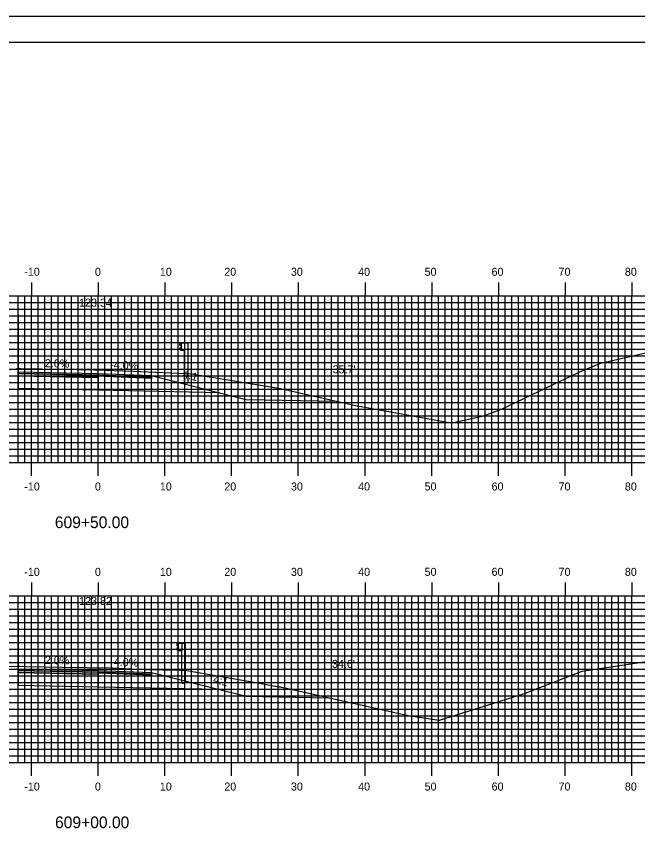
# Model space of a CAD drawing. Extents: x 842962 to 843305, y 363538 to 363758.
# Drawn here: x 843115.7 to 843208.7, y 363633.7 to 363757.6 of the extents above; entities that cross this region are included whole.
import ezdxf

# ---------------------------------------------------------------- set-up
doc = ezdxf.new("R2010")
doc.units = 0
for name, color, linetype in [('ANNOTATION', 7, 'Continuous'), ('BORDER', 7, 'Continuous'), ('D_Roadway_Centerline_Text', 7, 'Continuous'), ('D_Roadway_Edge_Shoulder', 7, 'Continuous'), ('D_Roadway_Edge_TW', 7, 'Continuous'), ('D_Roadway_FinishedGrade', 7, 'Continuous'), ('D_Roadway_Pavement', 7, 'Continuous'), ('D_Roadway_SubGrade', 7, 'Continuous'), ('D_Text_Standard', 7, 'Continuous'), ('H_V ANNOTATION', 7, 'Continuous'), ('M_Guardrail', 7, 'Continuous'), ('M_Roadway_Centerline', 7, 'Continuous'), ('MAJOR', 7, 'Continuous'), ('MINOR', 7, 'Continuous'), ('PLOT BOUNDARY', 7, 'Continuous'), ('S_Roadway_Centerline', 7, 'Continuous')]:
    doc.layers.add(name, color=color, linetype=linetype)

msp = doc.modelspace()

# ---------------------------------------------------------------- linework, layer by layer
at = {"layer": 'BORDER'}
msp.add_lwpolyline([(842978.31, 363543.72), (843298.31, 363543.72), (843298.31, 363753.72), (842978.31, 363753.72)], close=True, dxfattribs=at)
at = {"layer": 'D_Roadway_Edge_Shoulder'}
for p, q in [((843115.91, 363704.05), (843115.91, 363704.3)), ((843115.91, 363659.53), (843115.91, 363659.78))]:
    msp.add_line(p, q, dxfattribs=at)
for points in [[(843127.91, 363704.06), (843135.91, 363703.74), (843135.91, 363703.49), (843127.91, 363703.81)], [(843127.91, 363659.54), (843135.91, 363659.22), (843135.91, 363658.97), (843127.91, 363659.29)]]:
    msp.add_lwpolyline(points, close=True, dxfattribs=at)
at = {"layer": 'D_Roadway_Edge_TW'}
for points in [[(843115.91, 363704.3), (843127.91, 363704.06), (843127.91, 363703.81), (843115.91, 363704.05)], [(843115.91, 363659.78), (843127.91, 363659.54), (843127.91, 363659.29), (843115.91, 363659.53)]]:
    msp.add_lwpolyline(points, close=True, dxfattribs=at)
at = {"layer": 'D_Roadway_FinishedGrade'}
for points in [[(843146.09, 363701.19), (843150.08, 363700.19), (843163.64, 363699.92)], [(843146.09, 363656.68), (843150.08, 363655.68), (843162.48, 363655.43)]]:
    msp.add_lwpolyline(points, dxfattribs=at)
at = {"layer": 'D_Roadway_Pavement'}
for p, q in [((843115.91, 363703.71), (843115.91, 363704.05)), ((843115.91, 363659.2), (843115.91, 363659.53))]:
    msp.add_line(p, q, dxfattribs=at)
for points in [[(843115.91, 363704.05), (843127.91, 363703.81), (843127.91, 363703.47), (843115.91, 363703.71)], [(843127.91, 363703.81), (843135.91, 363703.49), (843135.91, 363703.32), (843127.91, 363703.64)], [(843115.91, 363659.53), (843127.91, 363659.29), (843127.91, 363658.96), (843115.91, 363659.2)], [(843127.91, 363659.29), (843135.91, 363658.97), (843135.91, 363658.8), (843127.91, 363659.12)]]:
    msp.add_lwpolyline(points, close=True, dxfattribs=at)
for points in [[(843127.91, 363703.81), (843127.91, 363703.47)], [(843127.91, 363703.81), (843127.91, 363703.47)], [(843127.91, 363659.29), (843127.91, 363658.96)], [(843127.91, 363659.29), (843127.91, 363658.96)]]:
    msp.add_lwpolyline(points, dxfattribs=at)
at = {"layer": 'D_Roadway_SubGrade'}
for p, q in [((843115.91, 363712.89), (843115.91, 363701.8)), ((843115.91, 363701.8), (843115.91, 363703.71)), ((843115.91, 363668.38), (843115.91, 363657.28)), ((843115.91, 363657.28), (843115.91, 363659.2))]:
    msp.add_line(p, q, dxfattribs=at)
for points in [[(843115.91, 363703.71), (843127.91, 363703.47), (843127.91, 363701.56), (843115.91, 363701.8)], [(843127.91, 363703.47), (843127.91, 363703.81), (843135.91, 363703.49), (843135.91, 363703.74), (843146.09, 363701.19), (843127.91, 363701.56)], [(843115.91, 363659.2), (843127.91, 363658.96), (843127.91, 363657.04), (843115.91, 363657.28)], [(843127.91, 363658.96), (843127.91, 363659.29), (843135.91, 363658.97), (843135.91, 363659.22), (843146.09, 363656.68), (843127.91, 363657.04)]]:
    msp.add_lwpolyline(points, close=True, dxfattribs=at)
at = {"layer": 'M_Guardrail'}
for p, q in [((843140.28, 363708.57), (843140.13, 363708.47)), ((843140.13, 363708.32), (843140.33, 363708.19)), ((843140.33, 363707.97), (843140.13, 363707.83)), ((843140.38, 363708.59), (843140.29, 363708.57)), ((843140.36, 363708.12), (843140.36, 363708.03)), ((843140.38, 363708.66), (843140.87, 363708.66)), ((843140.38, 363707.49), (843140.38, 363708.66)), ((843140.87, 363708.66), (843141.36, 363708.66)), ((843140.87, 363708.66), (843140.87, 363707.49)), ((843141.36, 363708.66), (843141.36, 363702.66)), ((843140.13, 363707.69), (843140.28, 363707.59)), ((843140.29, 363707.58), (843140.38, 363707.57)), ((843140.87, 363707.49), (843140.38, 363707.49)), ((843140.87, 363702.66), (843140.87, 363707.49)), ((843140.87, 363702.66), (843141.36, 363702.66)), ((843139.86, 363663.55), (843139.72, 363663.45)), ((843139.96, 363663.57), (843139.88, 363663.56)), ((843139.96, 363663.64), (843140.45, 363663.64)), ((843139.96, 363662.48), (843139.96, 363663.64)), ((843140.45, 363663.64), (843140.94, 363663.64)), ((843140.45, 363663.64), (843140.45, 363662.48)), ((843140.94, 363663.64), (843140.94, 363657.64)), ((843139.72, 363663.31), (843139.91, 363663.17)), ((843139.91, 363662.95), (843139.72, 363662.82)), ((843139.72, 363662.67), (843139.86, 363662.57)), ((843139.88, 363662.57), (843139.96, 363662.55)), ((843139.95, 363663.11), (843139.95, 363663.02)), ((843140.45, 363662.48), (843139.96, 363662.48)), ((843140.45, 363657.64), (843140.45, 363662.48)), ((843140.45, 363657.64), (843140.94, 363657.64))]:
    msp.add_line(p, q, dxfattribs=at)
for centre, major_axis, start_param, end_param in [((843140.18, 363708.39), (-0.0877, 0), 5.323254, 7.243116), ((843140.3, 363708.53), (-0.0417, 0), 4.886922, 5.323254), ((843140.28, 363708.12), (0.0789, 0), 0, 0.959931), ((843140.28, 363708.03), (0.0789, 0), 5.323254, 6.283185), ((843140.18, 363707.76), (-0.0877, 0), 5.323254, 7.243116), ((843140.3, 363707.62), (-0.0417, 0), 0.959931, 1.396263), ((843139.77, 363663.38), (-0.0877, 0), 5.323254, 7.243116), ((843139.89, 363663.52), (-0.0417, 0), 4.886922, 5.323254), ((843139.77, 363662.74), (-0.0877, 0), 5.323254, 7.243116), ((843139.89, 363662.61), (-0.0417, 0), 0.959931, 1.396263), ((843139.87, 363663.11), (0.0789, 0), 0, 0.959931), ((843139.87, 363663.02), (0.0789, 0), 5.323254, 6.283185)]:
    msp.add_ellipse(centre, major_axis=major_axis, ratio=0.995501, start_param=start_param, end_param=end_param, dxfattribs=at)
at = {"layer": 'MAJOR'}
for p, q in [((843117.91, 363717.73), (843117.91, 363715.72)), ((843127.91, 363717.73), (843127.91, 363715.72)), ((843137.91, 363717.73), (843137.91, 363715.72)), ((843147.91, 363717.73), (843147.91, 363715.72)), ((843157.91, 363717.73), (843157.91, 363715.72)), ((843167.91, 363717.73), (843167.91, 363715.72)), ((843177.91, 363717.73), (843177.91, 363715.72)), ((843187.91, 363717.73), (843187.91, 363715.72)), ((843197.91, 363717.73), (843197.91, 363715.72)), ((843207.91, 363717.73), (843207.91, 363715.72)), ((842987.91, 363715.72), (843267.91, 363715.72)), ((842987.91, 363715.72), (843267.91, 363715.72)), ((843117.91, 363690.72), (843117.91, 363715.72)), ((843127.91, 363690.72), (843127.91, 363715.72)), ((843137.91, 363690.72), (843137.91, 363715.72)), ((843147.91, 363690.72), (843147.91, 363715.72)), ((843157.91, 363690.72), (843157.91, 363715.72)), ((843167.91, 363690.72), (843167.91, 363715.72)), ((843177.91, 363690.72), (843177.91, 363715.72)), ((843187.91, 363690.72), (843187.91, 363715.72)), ((843197.91, 363690.72), (843197.91, 363715.72)), ((843207.91, 363690.72), (843207.91, 363715.72)), ((842987.91, 363710.72), (843267.91, 363710.72)), ((842987.91, 363705.72), (843267.91, 363705.72)), ((842987.91, 363700.72), (843267.91, 363700.72)), ((842987.91, 363695.72), (843267.91, 363695.72)), ((842987.91, 363690.72), (843267.91, 363690.72)), ((842987.91, 363690.72), (843267.91, 363690.72)), ((843117.91, 363688.72), (843117.91, 363690.72)), ((843127.91, 363688.72), (843127.91, 363690.72)), ((843137.91, 363688.72), (843137.91, 363690.72)), ((843147.91, 363688.72), (843147.91, 363690.72)), ((843157.91, 363688.72), (843157.91, 363690.72)), ((843167.91, 363688.72), (843167.91, 363690.72)), ((843177.91, 363688.72), (843177.91, 363690.72)), ((843187.91, 363688.72), (843187.91, 363690.72)), ((843197.91, 363688.72), (843197.91, 363690.72)), ((843207.91, 363688.72), (843207.91, 363690.72)), ((843117.91, 363672.73), (843117.91, 363670.72)), ((843127.91, 363672.73), (843127.91, 363670.72)), ((843137.91, 363672.73), (843137.91, 363670.72)), ((843147.91, 363672.73), (843147.91, 363670.72)), ((843157.91, 363672.73), (843157.91, 363670.72)), ((843167.91, 363672.73), (843167.91, 363670.72)), ((843177.91, 363672.73), (843177.91, 363670.72)), ((843187.91, 363672.73), (843187.91, 363670.72)), ((843197.91, 363672.73), (843197.91, 363670.72)), ((843207.91, 363672.73), (843207.91, 363670.72)), ((842987.91, 363670.72), (843267.91, 363670.72)), ((842987.91, 363670.72), (843267.91, 363670.72)), ((843117.91, 363645.72), (843117.91, 363670.72)), ((843127.91, 363645.72), (843127.91, 363670.72)), ((843137.91, 363645.72), (843137.91, 363670.72)), ((843147.91, 363645.72), (843147.91, 363670.72)), ((843157.91, 363645.72), (843157.91, 363670.72)), ((843167.91, 363645.72), (843167.91, 363670.72)), ((843177.91, 363645.72), (843177.91, 363670.72)), ((843187.91, 363645.72), (843187.91, 363670.72)), ((843197.91, 363645.72), (843197.91, 363670.72)), ((843207.91, 363645.72), (843207.91, 363670.72)), ((842987.91, 363665.72), (843267.91, 363665.72)), ((842987.91, 363660.72), (843267.91, 363660.72)), ((842987.91, 363655.72), (843267.91, 363655.72)), ((842987.91, 363650.72), (843267.91, 363650.72)), ((842987.91, 363645.72), (843267.91, 363645.72)), ((842987.91, 363645.72), (843267.91, 363645.72)), ((843117.91, 363643.72), (843117.91, 363645.72)), ((843127.91, 363643.72), (843127.91, 363645.72)), ((843137.91, 363643.72), (843137.91, 363645.72)), ((843147.91, 363643.72), (843147.91, 363645.72)), ((843157.91, 363643.72), (843157.91, 363645.72)), ((843167.91, 363643.72), (843167.91, 363645.72)), ((843177.91, 363643.72), (843177.91, 363645.72)), ((843187.91, 363643.72), (843187.91, 363645.72)), ((843197.91, 363643.72), (843197.91, 363645.72)), ((843207.91, 363643.72), (843207.91, 363645.72))]:
    msp.add_line(p, q, dxfattribs=at)
at = {"layer": 'MINOR'}
for p, q in [((843115.91, 363690.72), (843115.91, 363715.72)), ((843116.91, 363690.72), (843116.91, 363715.72)), ((843118.91, 363690.72), (843118.91, 363715.72)), ((843119.91, 363690.72), (843119.91, 363715.72)), ((843120.91, 363690.72), (843120.91, 363715.72)), ((843121.91, 363690.72), (843121.91, 363715.72)), ((843122.91, 363690.72), (843122.91, 363715.72)), ((843123.91, 363690.72), (843123.91, 363715.72)), ((843124.91, 363690.72), (843124.91, 363715.72)), ((843125.91, 363690.72), (843125.91, 363715.72)), ((843126.91, 363690.72), (843126.91, 363715.72)), ((843128.91, 363690.72), (843128.91, 363715.72)), ((843129.91, 363690.72), (843129.91, 363715.72)), ((843130.91, 363690.72), (843130.91, 363715.72)), ((843131.91, 363690.72), (843131.91, 363715.72)), ((843132.91, 363690.72), (843132.91, 363715.72)), ((843133.91, 363690.72), (843133.91, 363715.72)), ((843134.91, 363690.72), (843134.91, 363715.72)), ((843135.91, 363690.72), (843135.91, 363715.72)), ((843136.91, 363690.72), (843136.91, 363715.72)), ((843138.91, 363690.72), (843138.91, 363715.72)), ((843139.91, 363690.72), (843139.91, 363715.72)), ((843140.91, 363690.72), (843140.91, 363715.72)), ((843141.91, 363690.72), (843141.91, 363715.72)), ((843142.91, 363690.72), (843142.91, 363715.72)), ((843143.91, 363690.72), (843143.91, 363715.72)), ((843144.91, 363690.72), (843144.91, 363715.72)), ((843145.91, 363690.72), (843145.91, 363715.72)), ((843146.91, 363690.72), (843146.91, 363715.72)), ((843148.91, 363690.72), (843148.91, 363715.72)), ((843149.91, 363690.72), (843149.91, 363715.72)), ((843150.91, 363690.72), (843150.91, 363715.72)), ((843151.91, 363690.72), (843151.91, 363715.72)), ((843152.91, 363690.72), (843152.91, 363715.72)), ((843153.91, 363690.72), (843153.91, 363715.72)), ((843154.91, 363690.72), (843154.91, 363715.72)), ((843155.91, 363690.72), (843155.91, 363715.72)), ((843156.91, 363690.72), (843156.91, 363715.72)), ((843158.91, 363690.72), (843158.91, 363715.72)), ((843159.91, 363690.72), (843159.91, 363715.72)), ((843160.91, 363690.72), (843160.91, 363715.72)), ((843161.91, 363690.72), (843161.91, 363715.72)), ((843162.91, 363690.72), (843162.91, 363715.72)), ((843163.91, 363690.72), (843163.91, 363715.72)), ((843164.91, 363690.72), (843164.91, 363715.72)), ((843165.91, 363690.72), (843165.91, 363715.72)), ((843166.91, 363690.72), (843166.91, 363715.72)), ((843168.91, 363690.72), (843168.91, 363715.72)), ((843169.91, 363690.72), (843169.91, 363715.72)), ((843170.91, 363690.72), (843170.91, 363715.72)), ((843171.91, 363690.72), (843171.91, 363715.72)), ((843172.91, 363690.72), (843172.91, 363715.72)), ((843173.91, 363690.72), (843173.91, 363715.72)), ((843174.91, 363690.72), (843174.91, 363715.72)), ((843175.91, 363690.72), (843175.91, 363715.72)), ((843176.91, 363690.72), (843176.91, 363715.72)), ((843178.91, 363690.72), (843178.91, 363715.72)), ((843179.91, 363690.72), (843179.91, 363715.72)), ((843180.91, 363690.72), (843180.91, 363715.72)), ((843181.91, 363690.72), (843181.91, 363715.72)), ((843182.91, 363690.72), (843182.91, 363715.72)), ((843183.91, 363690.72), (843183.91, 363715.72)), ((843184.91, 363690.72), (843184.91, 363715.72)), ((843185.91, 363690.72), (843185.91, 363715.72)), ((843186.91, 363690.72), (843186.91, 363715.72)), ((843188.91, 363690.72), (843188.91, 363715.72)), ((843189.91, 363690.72), (843189.91, 363715.72)), ((843190.91, 363690.72), (843190.91, 363715.72)), ((843191.91, 363690.72), (843191.91, 363715.72)), ((843192.91, 363690.72), (843192.91, 363715.72)), ((843193.91, 363690.72), (843193.91, 363715.72)), ((843194.91, 363690.72), (843194.91, 363715.72)), ((843195.91, 363690.72), (843195.91, 363715.72)), ((843196.91, 363690.72), (843196.91, 363715.72)), ((843198.91, 363690.72), (843198.91, 363715.72)), ((843199.91, 363690.72), (843199.91, 363715.72)), ((843200.91, 363690.72), (843200.91, 363715.72)), ((843201.91, 363690.72), (843201.91, 363715.72)), ((843202.91, 363690.72), (843202.91, 363715.72)), ((843203.91, 363690.72), (843203.91, 363715.72)), ((843204.91, 363690.72), (843204.91, 363715.72)), ((843205.91, 363690.72), (843205.91, 363715.72)), ((843206.91, 363690.72), (843206.91, 363715.72)), ((842987.91, 363714.72), (843267.91, 363714.72)), ((842987.91, 363713.72), (843267.91, 363713.72)), ((842987.91, 363712.72), (843267.91, 363712.72)), ((842987.91, 363711.72), (843267.91, 363711.72)), ((842987.91, 363709.72), (843267.91, 363709.72)), ((842987.91, 363708.72), (843267.91, 363708.72)), ((842987.91, 363707.72), (843267.91, 363707.72)), ((842987.91, 363706.72), (843267.91, 363706.72)), ((842987.91, 363704.72), (843267.91, 363704.72)), ((842987.91, 363703.72), (843267.91, 363703.72)), ((842987.91, 363702.72), (843267.91, 363702.72)), ((842987.91, 363701.72), (843267.91, 363701.72)), ((842987.91, 363699.72), (843267.91, 363699.72)), ((842987.91, 363698.72), (843267.91, 363698.72)), ((842987.91, 363697.72), (843267.91, 363697.72)), ((842987.91, 363696.72), (843267.91, 363696.72)), ((842987.91, 363694.72), (843267.91, 363694.72)), ((842987.91, 363693.72), (843267.91, 363693.72)), ((842987.91, 363692.72), (843267.91, 363692.72)), ((842987.91, 363691.72), (843267.91, 363691.72)), ((842987.91, 363669.72), (843267.91, 363669.72)), ((843115.91, 363645.72), (843115.91, 363670.72)), ((843116.91, 363645.72), (843116.91, 363670.72)), ((843118.91, 363645.72), (843118.91, 363670.72)), ((843119.91, 363645.72), (843119.91, 363670.72)), ((843120.91, 363645.72), (843120.91, 363670.72)), ((843121.91, 363645.72), (843121.91, 363670.72)), ((843122.91, 363645.72), (843122.91, 363670.72)), ((843123.91, 363645.72), (843123.91, 363670.72)), ((843124.91, 363645.72), (843124.91, 363670.72)), ((843125.91, 363645.72), (843125.91, 363670.72)), ((843126.91, 363645.72), (843126.91, 363670.72)), ((843128.91, 363645.72), (843128.91, 363670.72)), ((843129.91, 363645.72), (843129.91, 363670.72)), ((843130.91, 363645.72), (843130.91, 363670.72)), ((843131.91, 363645.72), (843131.91, 363670.72)), ((843132.91, 363645.72), (843132.91, 363670.72)), ((843133.91, 363645.72), (843133.91, 363670.72)), ((843134.91, 363645.72), (843134.91, 363670.72)), ((843135.91, 363645.72), (843135.91, 363670.72)), ((843136.91, 363645.72), (843136.91, 363670.72)), ((843138.91, 363645.72), (843138.91, 363670.72)), ((843139.91, 363645.72), (843139.91, 363670.72)), ((843140.91, 363645.72), (843140.91, 363670.72)), ((843141.91, 363645.72), (843141.91, 363670.72)), ((843142.91, 363645.72), (843142.91, 363670.72)), ((843143.91, 363645.72), (843143.91, 363670.72)), ((843144.91, 363645.72), (843144.91, 363670.72)), ((843145.91, 363645.72), (843145.91, 363670.72)), ((843146.91, 363645.72), (843146.91, 363670.72)), ((843148.91, 363645.72), (843148.91, 363670.72)), ((843149.91, 363645.72), (843149.91, 363670.72)), ((843150.91, 363645.72), (843150.91, 363670.72)), ((843151.91, 363645.72), (843151.91, 363670.72)), ((843152.91, 363645.72), (843152.91, 363670.72)), ((843153.91, 363645.72), (843153.91, 363670.72)), ((843154.91, 363645.72), (843154.91, 363670.72)), ((843155.91, 363645.72), (843155.91, 363670.72)), ((843156.91, 363645.72), (843156.91, 363670.72)), ((843158.91, 363645.72), (843158.91, 363670.72)), ((843159.91, 363645.72), (843159.91, 363670.72)), ((843160.91, 363645.72), (843160.91, 363670.72)), ((843161.91, 363645.72), (843161.91, 363670.72)), ((843162.91, 363645.72), (843162.91, 363670.72)), ((843163.91, 363645.72), (843163.91, 363670.72)), ((843164.91, 363645.72), (843164.91, 363670.72)), ((843165.91, 363645.72), (843165.91, 363670.72)), ((843166.91, 363645.72), (843166.91, 363670.72)), ((843168.91, 363645.72), (843168.91, 363670.72)), ((843169.91, 363645.72), (843169.91, 363670.72)), ((843170.91, 363645.72), (843170.91, 363670.72)), ((843171.91, 363645.72), (843171.91, 363670.72)), ((843172.91, 363645.72), (843172.91, 363670.72)), ((843173.91, 363645.72), (843173.91, 363670.72)), ((843174.91, 363645.72), (843174.91, 363670.72)), ((843175.91, 363645.72), (843175.91, 363670.72)), ((843176.91, 363645.72), (843176.91, 363670.72)), ((843178.91, 363645.72), (843178.91, 363670.72)), ((843179.91, 363645.72), (843179.91, 363670.72)), ((843180.91, 363645.72), (843180.91, 363670.72)), ((843181.91, 363645.72), (843181.91, 363670.72)), ((843182.91, 363645.72), (843182.91, 363670.72)), ((843183.91, 363645.72), (843183.91, 363670.72)), ((843184.91, 363645.72), (843184.91, 363670.72)), ((843185.91, 363645.72), (843185.91, 363670.72)), ((843186.91, 363645.72), (843186.91, 363670.72)), ((843188.91, 363645.72), (843188.91, 363670.72)), ((843189.91, 363645.72), (843189.91, 363670.72)), ((843190.91, 363645.72), (843190.91, 363670.72)), ((843191.91, 363645.72), (843191.91, 363670.72)), ((843192.91, 363645.72), (843192.91, 363670.72)), ((843193.91, 363645.72), (843193.91, 363670.72)), ((843194.91, 363645.72), (843194.91, 363670.72)), ((843195.91, 363645.72), (843195.91, 363670.72)), ((843196.91, 363645.72), (843196.91, 363670.72)), ((843198.91, 363645.72), (843198.91, 363670.72)), ((843199.91, 363645.72), (843199.91, 363670.72)), ((843200.91, 363645.72), (843200.91, 363670.72)), ((843201.91, 363645.72), (843201.91, 363670.72)), ((843202.91, 363645.72), (843202.91, 363670.72)), ((843203.91, 363645.72), (843203.91, 363670.72)), ((843204.91, 363645.72), (843204.91, 363670.72)), ((843205.91, 363645.72), (843205.91, 363670.72)), ((843206.91, 363645.72), (843206.91, 363670.72)), ((842987.91, 363668.72), (843267.91, 363668.72)), ((842987.91, 363667.72), (843267.91, 363667.72)), ((842987.91, 363666.72), (843267.91, 363666.72)), ((842987.91, 363664.72), (843267.91, 363664.72)), ((842987.91, 363663.72), (843267.91, 363663.72)), ((842987.91, 363662.72), (843267.91, 363662.72)), ((842987.91, 363661.72), (843267.91, 363661.72)), ((842987.91, 363659.72), (843267.91, 363659.72)), ((842987.91, 363658.72), (843267.91, 363658.72)), ((842987.91, 363657.72), (843267.91, 363657.72)), ((842987.91, 363656.72), (843267.91, 363656.72)), ((842987.91, 363654.72), (843267.91, 363654.72)), ((842987.91, 363653.72), (843267.91, 363653.72)), ((842987.91, 363652.72), (843267.91, 363652.72)), ((842987.91, 363651.72), (843267.91, 363651.72)), ((842987.91, 363649.72), (843267.91, 363649.72)), ((842987.91, 363648.72), (843267.91, 363648.72)), ((842987.91, 363647.72), (843267.91, 363647.72)), ((842987.91, 363646.72), (843267.91, 363646.72))]:
    msp.add_line(p, q, dxfattribs=at)
at = {"layer": 'PLOT BOUNDARY'}
msp.add_lwpolyline([(842962.12, 363537.6), (843302.12, 363537.6), (843302.12, 363757.6), (842962.12, 363757.6)], close=True, dxfattribs=at)
at = {"layer": 'S_Roadway_Centerline'}
for points in [[(843115.65, 363704.79), (843116.3, 363704.83), (843119.41, 363704.77), (843127.35, 363704.63), (843133.21, 363704.4), (843142.06, 363704), (843142.44, 363703.92), (843147.1, 363703.15), (843155.25, 363701.82), (843166.5, 363699.28), (843166.75, 363699.22), (843167.32, 363699.11), (843180.5, 363696.72), (843180.96, 363696.67), (843185.66, 363697.71), (843188.36, 363698.72), (843196.21, 363702.48), (843200.76, 363704.62), (843203.28, 363705.59), (843213.27, 363707.92)], [(843110.99, 363660.08), (843116.11, 363660.15), (843117.18, 363660.13), (843122.48, 363660.03), (843130.09, 363659.9), (843134.82, 363659.69), (843140.25, 363659.59), (843141.19, 363659.54), (843151.53, 363657.71), (843154.73, 363657.14), (843155.06, 363657.08), (843155.19, 363657.06), (843155.36, 363657.02), (843156.15, 363656.85), (843174.38, 363652.76), (843178.69, 363652.13), (843179.04, 363652.07), (843179.08, 363652.08), (843179.85, 363652.31), (843191.66, 363656.04), (843200.45, 363659.4), (843212.04, 363661.17)]]:
    msp.add_lwpolyline(points, dxfattribs=at)

# ---------------------------------------------------------------- texts
at = {"layer": 'ANNOTATION'}
for s, rotation, p in [('2.0%', 358.8542, (843119.92, 363705.02)), ('-4.0%', 357.7094, (843129.7, 363704.79)), ('4:1', 345.9638, (843140.5, 363703.45)), ('2.0%', 358.8542, (843119.92, 363660.5)), ('-4.0%', 357.7094, (843129.7, 363660.27)), ('4:1', 345.9638, (843145.06, 363657.69))]:
    msp.add_text(s, height=1.2, rotation=rotation, dxfattribs=at).set_placement(p)
at = {"layer": 'D_Roadway_Centerline_Text'}
for s, p in [('123.34', (843125.06, 363714.09)), ('123.82', (843125.06, 363669.35))]:
    msp.add_text(s, height=1.2, dxfattribs=at).set_placement(p)
at = {"layer": 'D_Text_Standard'}
for s, p in [("35.7'", (843163.06, 363704.09)), ("34.6'", (843162.96, 363659.92))]:
    msp.add_text(s, height=1.2, dxfattribs=at).set_placement(p)
at = {"layer": 'H_V ANNOTATION'}
for s, height, p in [('-10', 1.2, (843116.84, 363718.72)), ('0', 1.2, (843127.43, 363718.72)), ('10', 1.2, (843137.16, 363718.72)), ('20', 1.2, (843146.82, 363718.72)), ('30', 1.2, (843156.81, 363718.72)), ('40', 1.2, (843166.88, 363718.72)), ('50', 1.2, (843176.84, 363718.72)), ('60', 1.2, (843186.88, 363718.72)), ('70', 1.2, (843196.92, 363718.72)), ('80', 1.2, (843206.86, 363718.72)), ('-10', 1.2, (843116.84, 363686.52)), ('0', 1.2, (843127.43, 363686.52)), ('10', 1.2, (843137.16, 363686.52)), ('20', 1.2, (843146.82, 363686.52)), ('30', 1.2, (843156.81, 363686.52)), ('40', 1.2, (843166.88, 363686.52)), ('50', 1.2, (843176.84, 363686.52)), ('60', 1.2, (843186.88, 363686.52)), ('70', 1.2, (843196.92, 363686.52)), ('80', 1.2, (843206.86, 363686.52)), ('609+50.00', 1.75, (843121.42, 363680.88)), ('-10', 1.2, (843116.84, 363673.72)), ('0', 1.2, (843127.43, 363673.72)), ('10', 1.2, (843137.16, 363673.72)), ('20', 1.2, (843146.82, 363673.72)), ('30', 1.2, (843156.81, 363673.72)), ('40', 1.2, (843166.88, 363673.72)), ('50', 1.2, (843176.84, 363673.72)), ('60', 1.2, (843186.88, 363673.72)), ('70', 1.2, (843196.92, 363673.72)), ('80', 1.2, (843206.86, 363673.72)), ('-10', 1.2, (843116.84, 363641.52)), ('0', 1.2, (843127.43, 363641.52)), ('10', 1.2, (843137.16, 363641.52)), ('20', 1.2, (843146.82, 363641.52)), ('30', 1.2, (843156.81, 363641.52)), ('40', 1.2, (843166.88, 363641.52)), ('50', 1.2, (843176.84, 363641.52)), ('60', 1.2, (843186.88, 363641.52)), ('70', 1.2, (843196.92, 363641.52)), ('80', 1.2, (843206.86, 363641.52)), ('609+00.00', 1.75, (843121.45, 363635.88))]:
    msp.add_text(s, height=height, dxfattribs=at).set_placement(p)
at = {"layer": 'M_Roadway_Centerline'}
for s, p in [('C', (843116.29, 363704.83)), ('L', (843116.3, 363704.83)), ('C', (843116.11, 363660.15)), ('L', (843116.11, 363660.14))]:
    msp.add_text(s, height=0.0146, dxfattribs=at).set_placement(p)

doc.saveas('drawing.dxf')
